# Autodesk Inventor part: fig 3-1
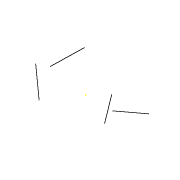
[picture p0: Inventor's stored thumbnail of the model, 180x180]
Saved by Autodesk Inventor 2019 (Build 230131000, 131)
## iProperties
Created: 2011-07
Part Number: fig 3-1
Material: Generic
Document SubType Name: Modeling
Designer: CadCim
Density: 1 g/cm^3
Appearance: Default
Author: CadCim
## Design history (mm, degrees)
sketch "Sketch1"
  geometry: L1 (-24.535, 0.895)-(-9.053, -12.994); L2 (-20.147, 3.302)-(-19.785, 19.15); L3 (5.706, 6.44)-(15.874, -7.118); L4 (12.565, -0.112)-(22.33, 7.212); 1 further point
  constraints: 8 end point, 1 perpendicular, 1 other
